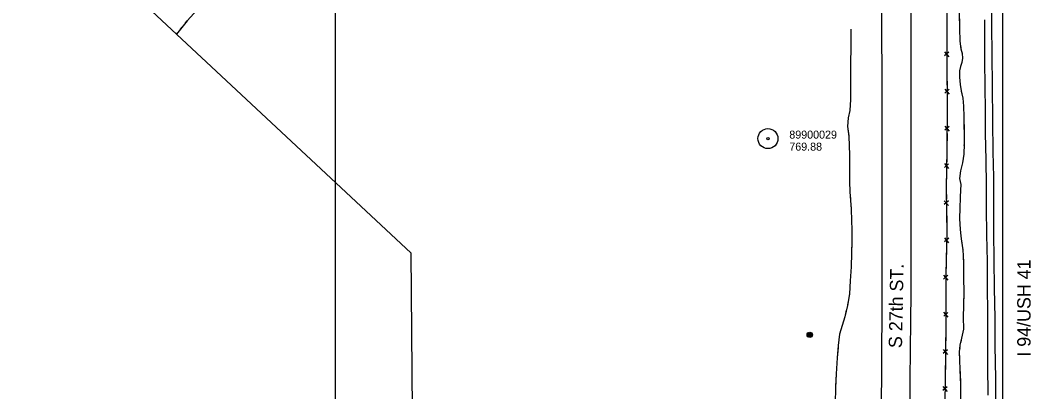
# Model space of a CAD drawing. Extents: x 591954 to 597000, y 198576 to 213500.
# Drawn here: x 593264 to 594021, y 202706 to 202984 of the extents above; entities that cross this region are included whole.
import ezdxf

# ---------------------------------------------------------------- set-up
doc = ezdxf.new("R2010")
doc.units = 0
for name, color, linetype in [('Level 10', 7, 'Continuous'), ('Level 11', 7, 'Continuous'), ('Level 14', 7, 'Continuous'), ('Level 15', 7, 'Continuous'), ('Level 19', 7, 'Continuous'), ('Level 3', 7, 'Continuous'), ('Level 4', 7, 'Continuous'), ('Level 6', 7, 'Continuous')]:
    doc.layers.add(name, color=color, linetype=linetype)

msp = doc.modelspace()

# ---------------------------------------------------------------- linework, layer by layer
at = {"layer": 'Level 10'}
for p, q in [((593500, 202500), (593500, 204000)), ((594000, 202500), (594000, 204000)), ((593500, 202000), (593500, 203500)), ((594000, 202000), (594000, 203500))]:
    msp.add_line(p, q, dxfattribs=at)
at = {"layer": 'Level 11'}
for points in [[(593931.14, 203000.49), (593931.15, 202980.29), (593931.2, 202957.71), (593931.12, 202935.56), (593931.2, 202912.24), (593931.19, 202888.86), (593931.17, 202867.94), (593931.21, 202846.92), (593931.13, 202823.99), (593931.08, 202802.27), (593931.05, 202779.89), (593930.89, 202758.64), (593930.69, 202737.17), (593930.53, 202714.66), (593930.48, 202694.96)], [(593991.48, 202999.61), (593991.7, 202980.4), (593991.83, 202957.82), (593992.12, 202934.77), (593992.37, 202908.47), (593992.7, 202885.33), (593993.08, 202866.44), (593993.04, 202845.67), (593993.19, 202825.35), (593993.49, 202804.33), (593993.66, 202783.28), (593994.05, 202760.9), (593994.19, 202740.11), (593994.55, 202715.61), (593994.7, 202695.28)], [(593909.24, 202990.41), (593909.24, 202967.6), (593909.32, 202949.83), (593909.46, 202929.34), (593909.44, 202911.46), (593909.45, 202895.03), (593909.56, 202871.26), (593909.51, 202849.59), (593909.54, 202829.67), (593909.53, 202808.58), (593909.47, 202788.46), (593909.42, 202762.62), (593909.24, 202737.3), (593909.1, 202719.1), (593908.91, 202698.56)], [(593986.28, 202984.34), (593986.34, 202967.83), (593986.49, 202951.71), (593986.61, 202935.82), (593986.89, 202914.97), (593986.98, 202899.33), (593987.27, 202879.3), (593987.51, 202860.49), (593987.69, 202843.11), (593987.88, 202823.15), (593988.28, 202803.37), (593988.44, 202784.7), (593988.65, 202764.44), (593988.74, 202744.59), (593988.75, 202725.49), (593988.85, 202703.22)]]:
    msp.add_lwpolyline(points, dxfattribs=at)
at = {"layer": 'Level 14'}
for centre, radius in [((593855.44, 202748.37), 2.02), ((593855.44, 202748.38), 1.52), ((593855.44, 202748.34), 1.01), ((593855.45, 202748.35), 0.502)]:
    msp.add_circle(centre, radius, dxfattribs=at)
at = {"layer": 'Level 15'}
for p, q in [((593956.42, 202960.29), (593959.65, 202956.56)), ((593959.66, 202960.11), (593956.48, 202957.32)), ((593956.57, 202932.4), (593959.84, 202928.72)), ((593959.81, 202932.27), (593956.67, 202929.44)), ((593956.58, 202904.58), (593959.79, 202900.83)), ((593959.82, 202904.38), (593956.62, 202901.61)), ((593956.28, 202876.73), (593959.46, 202872.96)), ((593959.52, 202876.51), (593956.31, 202873.76)), ((593956.09, 202848.82), (593959.38, 202845.15)), ((593959.33, 202848.7), (593956.2, 202845.86)), ((593959.56, 202820.78), (593956.32, 202818.07)), ((593956.33, 202821.04), (593959.47, 202817.23)), ((593955.6, 202793.14), (593958.85, 202789.43)), ((593958.84, 202792.97), (593955.68, 202790.17)), ((593955.72, 202765.28), (593958.97, 202761.56)), ((593958.96, 202765.12), (593955.8, 202762.31)), ((593955.4, 202737.45), (593958.59, 202733.68)), ((593958.64, 202737.23), (593955.43, 202734.48)), ((593955.11, 202709.58), (593958.31, 202705.83)), ((593958.34, 202709.38), (593955.15, 202706.61))]:
    msp.add_line(p, q, dxfattribs=at)
for points in [[(593955.5, 203249.96), (593955.91, 203230.5), (593956.02, 203198.71), (593956.95, 203166.55), (593957.82, 203134.64), (593957.8, 203105.11), (593957.85, 203077.06), (593958.13, 203045.84), (593958.62, 203014.11), (593958.22, 202982.52), (593958.13, 202950.82), (593958.43, 202919.33), (593958.18, 202887.35), (593957.73, 202857.12), (593958.15, 202824.07), (593957.34, 202792.85), (593957.47, 202762.26), (593957.05, 202730.71), (593956.73, 202697.45)], [(593958.23, 202982.72), (593958.22, 202982.52), (593958.19, 202971.4)], [(593958.19, 202971.4), (593958.16, 202961.44)], [(593958.15, 202954.86), (593958.13, 202950.82), (593958.2, 202943.54)], [(593958.2, 202943.54), (593958.3, 202933.58)], [(593958.36, 202927), (593958.43, 202919.33), (593958.41, 202915.68)], [(593958.41, 202915.68), (593958.33, 202905.72)], [(593958.28, 202899.14), (593958.19, 202887.82)], [(593958.19, 202887.82), (593958.18, 202887.35), (593958.04, 202877.86)], [(593957.94, 202871.28), (593957.77, 202859.96)], [(593957.77, 202859.96), (593957.73, 202857.12), (593957.82, 202850.01)], [(593957.9, 202843.43), (593958.05, 202832.11)], [(593958.05, 202832.11), (593958.15, 202824.07), (593958.1, 202822.15)], [(593957.93, 202815.57), (593957.63, 202804.25)], [(593957.63, 202804.25), (593957.37, 202794.3)], [(593957.36, 202787.72), (593957.41, 202776.4)], [(593957.41, 202776.4), (593957.45, 202766.44)], [(593957.44, 202759.86), (593957.29, 202748.54)], [(593957.29, 202748.54), (593957.15, 202738.58)], [(593957.07, 202732), (593957.05, 202730.71), (593956.95, 202720.68)], [(593956.95, 202720.68), (593956.86, 202710.72)]]:
    msp.add_lwpolyline(points, dxfattribs=at)
at = {"layer": 'Level 19'}
for points in [[(593511.97, 203131.66), (593504.48, 203120.26), (593492.65, 203102.94), (593481.16, 203087.92), (593470.07, 203073.93), (593455.76, 203060.18), (593443.79, 203046.52), (593431.28, 203030.93), (593417.56, 203014.74), (593403.87, 203000.34), (593388.78, 202983.55), (593380.83, 202973.51)], [(593966.69, 203010.33), (593966.84, 203001.21), (593967.39, 202989.15), (593967.58, 202981.35)], [(593967.39, 202989.15), (593967.67, 202977.82), (593967.93, 202968.21), (593968.62, 202962.67), (593969.73, 202959.04), (593969.96, 202955.64), (593969.43, 202952.3), (593968.4, 202949.41), (593967.68, 202946.01), (593967.72, 202941.33), (593968.18, 202935.82), (593968.78, 202931.11), (593970.08, 202925.65), (593970.65, 202919.74), (593970.85, 202911.55), (593971.04, 202900.28), (593971.03, 202891.32), (593970.85, 202883.79), (593969.84, 202877.2), (593968.31, 202871.15), (593967.71, 202865.57), (593968.59, 202860.87), (593968.41, 202856.84), (593968.06, 202851.34), (593967.82, 202843.32), (593967.61, 202835.38), (593968.06, 202827.23), (593968.94, 202820.17), (593970.04, 202812.12), (593970.53, 202802.96), (593970.66, 202791.37), (593970.82, 202780.07), (593970.67, 202770.28), (593970.49, 202761.7), (593970.6, 202752.52), (593969.24, 202745.96), (593968.02, 202740.58), (593967.5, 202735.29), (593967.6, 202729.69), (593968.02, 202722.04), (593968.41, 202710.92), (593968.4, 202701.98)], [(593387.56, 202982.02), (593388.78, 202983.55), (593388.81, 202983.58)], [(593380.83, 202973.51), (593381.36, 202974.18)], [(593383.84, 202977.31), (593385.08, 202978.88)], [(593886.25, 202977.21), (593886.13, 202965.02), (593886.02, 202950.34), (593885.91, 202935.33), (593885.98, 202924.66), (593885.38, 202916.41), (593884.08, 202910.8), (593883.8, 202904.36), (593884.65, 202896.95), (593884.95, 202890.06), (593885.12, 202882.81), (593885.1, 202873.52), (593885.11, 202863.25), (593885.47, 202855.52), (593885.99, 202848.99), (593886.4, 202842.57), (593886.73, 202834.07), (593887.04, 202827.06), (593886.97, 202818.99), (593886.76, 202809.47), (593886.46, 202799.35), (593885.81, 202788.77), (593885.17, 202779.11), (593883.64, 202770.32), (593881.59, 202761.78), (593879.6, 202755.33), (593877.73, 202748.84), (593876.83, 202740.4), (593875.98, 202731.07), (593875.25, 202719.27), (593874.66, 202708.6), (593874.52, 202697.08)], [(593886.25, 202977.21), (593886.13, 202965.02), (593886.02, 202950.34), (593886, 202948.21)], [(593967.68, 202977.35), (593967.73, 202975.35)], [(593967.85, 202971.35), (593967.9, 202969.35)], [(593968.29, 202965.37), (593968.53, 202963.39)], [(593969.58, 202959.54), (593969.73, 202959.04), (593969.96, 202955.64), (593969.43, 202952.3), (593968.4, 202949.41), (593967.68, 202946.01), (593967.72, 202941.33), (593968.18, 202935.82), (593968.78, 202931.11), (593968.83, 202930.93)], [(593885.97, 202944.21), (593885.96, 202942.21)], [(593885.93, 202938.21), (593885.91, 202936.21)], [(593885.97, 202926.21), (593885.98, 202924.66), (593885.38, 202916.41), (593884.08, 202910.8), (593883.8, 202904.36), (593884.59, 202897.43)], [(593885.93, 202932.21), (593885.94, 202930.21)], [(593968.83, 202930.93), (593970.08, 202925.65), (593970.65, 202919.74), (593970.85, 202911.55), (593971.01, 202902.1)], [(593884.59, 202897.43), (593884.65, 202896.95), (593884.95, 202890.06), (593885.12, 202882.81), (593885.1, 202873.52), (593885.1, 202868.44)], [(593971.03, 202898.1), (593971.03, 202896.1)], [(593971.03, 202892.1), (593971.03, 202891.32), (593971, 202890.11)], [(593970.91, 202886.11), (593970.86, 202884.11)], [(593970.3, 202880.15), (593969.84, 202877.2), (593968.31, 202871.15), (593967.71, 202865.57), (593968.59, 202860.87), (593968.41, 202856.84), (593968.07, 202851.5)], [(593885.11, 202864.44), (593885.11, 202863.25), (593885.15, 202862.44)], [(593885.33, 202858.45), (593885.43, 202856.45)], [(593885.72, 202852.46), (593885.88, 202850.47)], [(593968.07, 202851.5), (593968.06, 202851.34), (593967.82, 202843.32), (593967.61, 202835.38), (593968.06, 202827.23), (593968.64, 202822.56)], [(593886.15, 202846.48), (593886.4, 202842.57), (593886.73, 202834.07), (593887.04, 202827.06), (593886.97, 202818.99), (593886.94, 202817.5)], [(593886.94, 202817.5), (593886.76, 202809.47), (593886.46, 202799.35), (593885.81, 202788.77), (593885.8, 202788.52)], [(593969.15, 202818.59), (593969.43, 202816.61)], [(593969.97, 202812.65), (593970.04, 202812.12), (593970.12, 202810.65)], [(593970.33, 202806.66), (593970.44, 202804.66)], [(593970.56, 202800.67), (593970.66, 202791.37), (593970.82, 202780.07), (593970.69, 202771.67)], [(593885.53, 202784.53), (593885.4, 202782.54)], [(593885.08, 202778.55), (593884.73, 202776.58)], [(593884.04, 202772.64), (593883.7, 202770.67)], [(593970.69, 202771.67), (593970.67, 202770.28), (593970.49, 202761.7), (593970.6, 202752.52), (593969.24, 202745.96), (593968.54, 202742.89)], [(593882.79, 202766.78), (593881.59, 202761.78), (593879.6, 202755.33), (593877.73, 202748.84), (593876.83, 202740.4), (593876.66, 202738.54)], [(593876.66, 202738.54), (593875.98, 202731.07), (593875.25, 202719.27), (593874.71, 202709.61)], [(593967.86, 202738.96), (593967.66, 202736.96)], [(593967.54, 202732.97), (593967.57, 202730.97)], [(593967.74, 202726.98), (593967.85, 202724.98)], [(593968.05, 202720.99), (593968.41, 202710.92), (593968.4, 202701.98), (593967.88, 202692.37), (593967.86, 202692.01)]]:
    msp.add_lwpolyline(points, dxfattribs=at)
at = {"layer": 'Level 4'}
for points in [[(593556.37, 202809.78), (592771.71, 203541.61), (592770.19, 203809.11)], [(593556.37, 202809.78), (593560.99, 202276.92)]]:
    msp.add_lwpolyline(points, dxfattribs=at)
at = {"layer": 'Level 6'}
for radius in [7.5, 7.5, 0.96, 0.96]:
    msp.add_circle((593824.09, 202895.32), radius, dxfattribs=at)

# ---------------------------------------------------------------- texts
at = {"layer": 'Level 3'}
for s, rotation, p in [('S 27th ST.', 88.88587, (593924.54, 202738.36)), ('I 94/USH 41', 90, (594020.93, 202732.02))]:
    msp.add_text(s, height=10, rotation=rotation, dxfattribs=at).set_placement(p)
at = {"layer": 'Level 6'}
for s, p in [('89900029', (593840.09, 202895.32)), ('89900029', (593840.09, 202895.32)), ('769.88', (593840.09, 202886.32)), ('769.88', (593840.09, 202886.32))]:
    msp.add_text(s, height=6, dxfattribs=at).set_placement(p)

doc.saveas('drawing.dxf')
